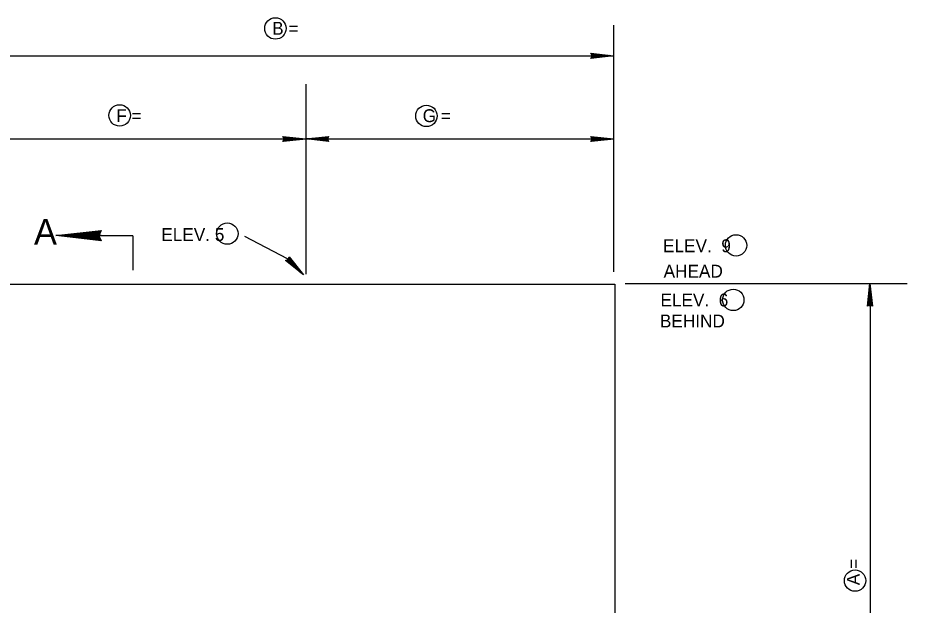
# Model space of a CAD drawing. Extents: x 1.6 to 6.29, y 2.8 to 7.08.
# Drawn here: x 2.935 to 3.8, y 5.479 to 6.051 of the extents above; entities that cross this region are included whole.
import ezdxf

# ---------------------------------------------------------------- set-up
doc = ezdxf.new("R2010")
doc.units = 0
doc.layers.add('Level 1', color=7, linetype='Continuous')
doc.layers.add('Level 5', color=7, linetype='Continuous')

msp = doc.modelspace()

# ---------------------------------------------------------------- linework, layer by layer
at = {"layer": 'Level 1'}
for p, q in [((3.51433, 5.80408), (3.51433, 6.04392)), ((2.90767, 6.01425), (3.22592, 6.01425)), ((3.22592, 6.01425), (3.51225, 6.01425)), ((3.492, 6.01667), (3.51425, 6.01425)), ((3.49317, 6.01425), (3.492, 6.01667)), ((3.492, 6.01425), (3.51425, 6.01425)), ((3.51425, 6.01425), (3.492, 6.01175)), ((3.492, 6.01175), (3.49317, 6.01425)), ((3.49233, 6.01283), (3.50783, 6.0145)), ((3.49242, 6.01633), (3.509, 6.0145)), ((3.49242, 6.01625), (3.509, 6.01442)), ((3.49242, 6.01617), (3.509, 6.01433)), ((3.49242, 6.01592), (3.509, 6.01408)), ((3.49242, 6.01258), (3.50783, 6.01425)), ((3.49242, 6.01233), (3.50792, 6.014)), ((3.4925, 6.01642), (3.509, 6.01458)), ((3.4925, 6.01208), (3.50792, 6.01383)), ((3.49292, 6.01325), (3.4925, 6.01217)), ((3.49358, 6.01442), (3.49258, 6.016)), ((3.49258, 6.016), (3.49308, 6.01567)), ((3.49333, 6.01417), (3.49292, 6.01325)), ((3.49783, 6.01517), (3.493, 6.01542)), ((3.493, 6.01542), (3.50067, 6.01483)), ((3.49308, 6.01567), (3.49358, 6.01483)), ((3.5045, 6.01442), (3.49308, 6.01325)), ((3.49308, 6.01325), (3.49358, 6.01442)), ((3.49325, 6.015), (3.49783, 6.01517)), ((3.49992, 6.01483), (3.49325, 6.015)), ((3.49325, 6.01367), (3.5045, 6.01442)), ((3.49867, 6.01367), (3.49325, 6.01367)), ((3.49367, 6.01575), (3.49333, 6.01417)), ((3.4935, 6.01467), (3.49992, 6.01483)), ((3.4935, 6.0145), (3.50342, 6.01467)), ((3.5015, 6.0145), (3.4935, 6.01467)), ((3.51125, 6.01408), (3.4935, 6.014)), ((3.4935, 6.014), (3.49867, 6.01367)), ((3.49358, 6.01483), (3.49408, 6.01508)), ((3.49408, 6.01508), (3.49367, 6.01575)), ((3.50067, 6.01483), (3.5105, 6.01442)), ((3.50333, 6.01442), (3.5015, 6.0145)), ((3.50342, 6.01467), (3.50333, 6.01442)), ((3.5105, 6.01442), (3.5085, 6.01383)), ((3.5085, 6.01383), (3.51125, 6.01408)), ((3.21483, 5.98658), (3.21483, 5.80158)), ((3.1925, 5.93567), (3.21475, 5.93325)), ((3.19367, 5.93325), (3.1925, 5.93567)), ((3.19292, 5.93533), (3.2095, 5.9335)), ((3.19292, 5.93525), (3.2095, 5.93342)), ((3.19292, 5.93517), (3.2095, 5.93333)), ((3.19292, 5.93492), (3.2095, 5.93308)), ((3.193, 5.93542), (3.2095, 5.93358)), ((3.19408, 5.93342), (3.19308, 5.935)), ((3.19308, 5.935), (3.19358, 5.93467)), ((3.19358, 5.93467), (3.19408, 5.93383)), ((3.19417, 5.93475), (3.19383, 5.93317)), ((3.19458, 5.93408), (3.19417, 5.93475)), ((3.21492, 5.93325), (3.237, 5.93575)), ((3.2365, 5.93533), (3.22117, 5.93367)), ((3.2365, 5.93517), (3.22117, 5.9335)), ((3.23658, 5.93492), (3.22125, 5.93325)), ((3.23658, 5.93467), (3.22125, 5.933)), ((3.237, 5.93575), (3.23583, 5.93325)), ((3.236, 5.93425), (3.2365, 5.93533)), ((3.49208, 5.93567), (3.51433, 5.93325)), ((3.49325, 5.93325), (3.49208, 5.93567)), ((3.4925, 5.93533), (3.50908, 5.9335)), ((3.4925, 5.93525), (3.50908, 5.93342)), ((3.4925, 5.93517), (3.50908, 5.93333)), ((3.4925, 5.93492), (3.50908, 5.93308)), ((3.49258, 5.93542), (3.50908, 5.93358)), ((3.49367, 5.93342), (3.49267, 5.935)), ((3.49267, 5.935), (3.49317, 5.93467)), ((3.49317, 5.93467), (3.49367, 5.93383)), ((3.49375, 5.93475), (3.49342, 5.93317)), ((3.49417, 5.93408), (3.49375, 5.93475)), ((2.90767, 5.93325), (3.51433, 5.93325)), ((3.1925, 5.93325), (3.21475, 5.93325)), ((3.21475, 5.93325), (3.1925, 5.93075)), ((3.1925, 5.93075), (3.19367, 5.93325)), ((3.19283, 5.93183), (3.20833, 5.9335)), ((3.19292, 5.93158), (3.20833, 5.93325)), ((3.19292, 5.93133), (3.20842, 5.933)), ((3.193, 5.93108), (3.20842, 5.93283)), ((3.19342, 5.93225), (3.193, 5.93117)), ((3.19383, 5.93317), (3.19342, 5.93225)), ((3.19833, 5.93417), (3.1935, 5.93442)), ((3.1935, 5.93442), (3.20117, 5.93383)), ((3.205, 5.93342), (3.19358, 5.93225)), ((3.19358, 5.93225), (3.19408, 5.93342)), ((3.19375, 5.934), (3.19833, 5.93417)), ((3.20042, 5.93383), (3.19375, 5.934)), ((3.19375, 5.93267), (3.205, 5.93342)), ((3.19917, 5.93267), (3.19375, 5.93267)), ((3.194, 5.93367), (3.20042, 5.93383)), ((3.194, 5.9335), (3.20392, 5.93367)), ((3.202, 5.9335), (3.194, 5.93367)), ((3.21175, 5.93308), (3.194, 5.933)), ((3.194, 5.933), (3.19917, 5.93267)), ((3.19408, 5.93383), (3.19458, 5.93408)), ((3.20117, 5.93383), (3.211, 5.93342)), ((3.20383, 5.93342), (3.202, 5.9335)), ((3.20392, 5.93367), (3.20383, 5.93342)), ((3.211, 5.93342), (3.209, 5.93283)), ((3.209, 5.93283), (3.21175, 5.93308)), ((3.237, 5.93325), (3.21492, 5.93325)), ((3.237, 5.93083), (3.21492, 5.93325)), ((3.22058, 5.93367), (3.21792, 5.93342)), ((3.21792, 5.93342), (3.2355, 5.9335)), ((3.21858, 5.93308), (3.22058, 5.93367)), ((3.22842, 5.93267), (3.21858, 5.93308)), ((3.2365, 5.93117), (3.22008, 5.933)), ((3.2365, 5.93125), (3.22008, 5.933)), ((3.2365, 5.93108), (3.22008, 5.93292)), ((3.23658, 5.93158), (3.22017, 5.93333)), ((3.2365, 5.93133), (3.22017, 5.93317)), ((3.2245, 5.933), (3.23583, 5.93425)), ((3.23575, 5.93383), (3.2245, 5.933)), ((3.22567, 5.93283), (3.22567, 5.93308)), ((3.22567, 5.93308), (3.22758, 5.933)), ((3.2355, 5.933), (3.22567, 5.93283)), ((3.22758, 5.933), (3.2355, 5.93283)), ((3.23592, 5.93208), (3.22842, 5.93267)), ((3.2355, 5.93283), (3.22917, 5.93267)), ((3.22917, 5.93267), (3.23575, 5.9325)), ((3.2355, 5.9335), (3.23033, 5.93383)), ((3.23033, 5.93383), (3.23575, 5.93383)), ((3.23575, 5.9325), (3.23108, 5.93233)), ((3.23108, 5.93233), (3.23592, 5.93208)), ((3.23542, 5.93267), (3.23483, 5.93242)), ((3.23483, 5.93242), (3.23525, 5.93175)), ((3.23525, 5.93175), (3.23558, 5.93333)), ((3.23583, 5.93425), (3.23542, 5.933)), ((3.23542, 5.933), (3.23633, 5.9315)), ((3.23583, 5.93183), (3.23542, 5.93267)), ((3.23558, 5.93333), (3.236, 5.93425)), ((3.23583, 5.93325), (3.237, 5.93083)), ((3.23633, 5.9315), (3.23583, 5.93183)), ((3.49208, 5.93325), (3.51433, 5.93325)), ((3.51433, 5.93325), (3.49208, 5.93075)), ((3.49208, 5.93075), (3.49325, 5.93325)), ((3.49242, 5.93183), (3.50792, 5.9335)), ((3.4925, 5.93158), (3.50792, 5.93325)), ((3.4925, 5.93133), (3.508, 5.933)), ((3.49258, 5.93108), (3.508, 5.93283)), ((3.493, 5.93225), (3.49258, 5.93117)), ((3.49342, 5.93317), (3.493, 5.93225)), ((3.49792, 5.93417), (3.49308, 5.93442)), ((3.49308, 5.93442), (3.50075, 5.93383)), ((3.50458, 5.93342), (3.49317, 5.93225)), ((3.49317, 5.93225), (3.49367, 5.93342)), ((3.49333, 5.934), (3.49792, 5.93417)), ((3.5, 5.93383), (3.49333, 5.934)), ((3.49333, 5.93267), (3.50458, 5.93342)), ((3.49875, 5.93267), (3.49333, 5.93267)), ((3.49358, 5.93367), (3.5, 5.93383)), ((3.49358, 5.9335), (3.5035, 5.93367)), ((3.50158, 5.9335), (3.49358, 5.93367)), ((3.51133, 5.93308), (3.49358, 5.933)), ((3.49358, 5.933), (3.49875, 5.93267)), ((3.49367, 5.93383), (3.49417, 5.93408)), ((3.50075, 5.93383), (3.51058, 5.93342)), ((3.50342, 5.93342), (3.50158, 5.9335)), ((3.5035, 5.93367), (3.50342, 5.93342)), ((3.51058, 5.93342), (3.50858, 5.93283)), ((3.50858, 5.93283), (3.51133, 5.93308)), ((2.97158, 5.83917), (3.01575, 5.84408)), ((2.983, 5.83992), (2.97758, 5.83942)), ((2.97758, 5.83942), (3.01275, 5.83958)), ((2.97892, 5.83883), (2.983, 5.83992)), ((3.01475, 5.84333), (2.98408, 5.84)), ((3.01483, 5.84292), (2.98417, 5.83958)), ((3.01492, 5.84242), (2.98433, 5.83908)), ((3.015, 5.84192), (2.98433, 5.83858)), ((2.99083, 5.83867), (3.0135, 5.84117)), ((3.01333, 5.84025), (2.99083, 5.83867)), ((3.01275, 5.83958), (3.0025, 5.84025)), ((3.0025, 5.84025), (3.01333, 5.84025)), ((3.0135, 5.84117), (3.01267, 5.83867)), ((3.01292, 5.83925), (3.01383, 5.84117)), ((3.01575, 5.84408), (3.01342, 5.83908)), ((3.01383, 5.84117), (3.01475, 5.84333)), ((3.01575, 5.83917), (2.97158, 5.83917)), ((3.01575, 5.83425), (2.97158, 5.83917)), ((2.99858, 5.838), (2.97892, 5.83883)), ((3.01483, 5.83517), (2.98192, 5.83867)), ((3.01483, 5.835), (2.98192, 5.83858)), ((3.01475, 5.83483), (2.98192, 5.83842)), ((3.01492, 5.83575), (2.98208, 5.83933)), ((3.01483, 5.83533), (2.98208, 5.839)), ((2.99308, 5.83833), (2.99317, 5.83883)), ((3.01275, 5.83858), (2.99308, 5.83833)), ((2.99317, 5.83883), (2.997, 5.83858)), ((2.997, 5.83858), (3.01275, 5.83833)), ((3.01367, 5.83683), (2.99858, 5.838)), ((3.01275, 5.83833), (3.00008, 5.83792)), ((3.00008, 5.83792), (3.01333, 5.83767)), ((3.01333, 5.83767), (3.004, 5.83733)), ((3.004, 5.83733), (3.01367, 5.83683)), ((3.01267, 5.838), (3.0115, 5.8375)), ((3.0115, 5.8375), (3.01225, 5.83608)), ((3.01225, 5.83608), (3.01292, 5.83925)), ((3.01267, 5.83867), (3.0145, 5.83558)), ((3.0135, 5.83625), (3.01267, 5.838)), ((3.01342, 5.83908), (3.01575, 5.83425)), ((3.0145, 5.83558), (3.0135, 5.83625)), ((3.04658, 5.839), (3.014, 5.839)), ((3.04658, 5.839), (3.04658, 5.80558)), ((3.19517, 5.81492), (3.19775, 5.81583)), ((3.21267, 5.80092), (3.19517, 5.81492)), ((3.19575, 5.81483), (3.20792, 5.80517)), ((3.19692, 5.81533), (3.19583, 5.81483)), ((3.19592, 5.815), (3.208, 5.80525)), ((3.19608, 5.81525), (3.20817, 5.8055)), ((3.19617, 5.81542), (3.20833, 5.80567)), ((3.19692, 5.81667), (3.21267, 5.80092)), ((3.19783, 5.81567), (3.19692, 5.81533)), ((3.197, 5.81525), (3.19817, 5.81567)), ((3.20592, 5.808), (3.197, 5.81525)), ((3.20125, 5.81158), (3.19742, 5.81542)), ((3.19742, 5.81542), (3.20592, 5.808)), ((3.19775, 5.81583), (3.19867, 5.81842)), ((3.19917, 5.81658), (3.19783, 5.81567)), ((3.21042, 5.80292), (3.19783, 5.81542)), ((3.19783, 5.81542), (3.20125, 5.81158)), ((3.19817, 5.81567), (3.19858, 5.8175)), ((3.19817, 5.81583), (3.20533, 5.80892)), ((3.203, 5.8115), (3.19833, 5.81633)), ((3.19833, 5.81633), (3.20175, 5.81317)), ((3.20383, 5.81017), (3.19833, 5.81592)), ((3.19833, 5.81592), (3.203, 5.8115)), ((3.19842, 5.81758), (3.20883, 5.80458)), ((3.19875, 5.81692), (3.1985, 5.816)), ((3.20175, 5.81317), (3.1985, 5.81683)), ((3.1985, 5.81683), (3.2035, 5.811)), ((3.1985, 5.816), (3.199, 5.81583)), ((3.19858, 5.81775), (3.209, 5.80475)), ((3.19858, 5.8175), (3.19875, 5.81692)), ((3.19867, 5.81842), (3.21267, 5.80092)), ((3.19867, 5.81783), (3.20908, 5.80475)), ((3.19875, 5.81783), (3.20917, 5.80483)), ((3.19883, 5.81783), (3.20917, 5.80492)), ((3.199, 5.81583), (3.19917, 5.81658)), ((3.2035, 5.811), (3.21017, 5.80375)), ((3.20508, 5.80875), (3.20383, 5.81017)), ((3.20533, 5.80892), (3.20508, 5.80875)), ((3.21017, 5.80375), (3.20833, 5.80475)), ((3.20833, 5.80475), (3.21042, 5.80292)), ((2.91025, 5.79208), (3.22917, 5.79208)), ((3.22917, 5.79208), (3.51525, 5.79208)), ((3.51525, 5.792), (3.51525, 5.28792)), ((3.5255, 5.7925), (3.79975, 5.7925)), ((3.76108, 5.77042), (3.7635, 5.7925)), ((3.76292, 5.779), (3.76342, 5.78883)), ((3.76342, 5.78883), (3.76392, 5.78675)), ((3.7635, 5.77042), (3.7635, 5.7925)), ((3.7635, 5.7925), (3.766, 5.77042)), ((3.76392, 5.78675), (3.76367, 5.7895)), ((3.76367, 5.7895), (3.76375, 5.77192)), ((3.76367, 5.78783), (3.76367, 5.13442)), ((3.76142, 5.77092), (3.76317, 5.78733)), ((3.76142, 5.77083), (3.76325, 5.78733)), ((3.7615, 5.77083), (3.76333, 5.78733)), ((3.76167, 5.77083), (3.76342, 5.78725)), ((3.76183, 5.77083), (3.76367, 5.78725)), ((3.76242, 5.77142), (3.76292, 5.779)), ((3.76325, 5.77192), (3.76308, 5.78175)), ((3.76308, 5.78175), (3.76342, 5.78167)), ((3.76325, 5.77983), (3.76308, 5.77192)), ((3.76492, 5.77075), (3.76325, 5.78608)), ((3.76342, 5.78167), (3.76325, 5.77983)), ((3.76408, 5.77167), (3.76333, 5.78292)), ((3.76333, 5.78292), (3.7645, 5.7715)), ((3.76517, 5.77083), (3.7635, 5.78617)), ((3.76542, 5.77083), (3.76375, 5.78625)), ((3.76567, 5.77092), (3.76392, 5.78625)), ((3.7635, 5.77158), (3.76108, 5.77042)), ((3.76333, 5.772), (3.76175, 5.771)), ((3.76175, 5.771), (3.76208, 5.7715)), ((3.76275, 5.7725), (3.762, 5.77217)), ((3.762, 5.77217), (3.76358, 5.77183)), ((3.76208, 5.7715), (3.76292, 5.772)), ((3.76267, 5.77625), (3.76242, 5.77142)), ((3.76275, 5.77167), (3.76267, 5.77625)), ((3.76292, 5.77825), (3.76275, 5.77167)), ((3.76292, 5.772), (3.76275, 5.7725)), ((3.76308, 5.77192), (3.76292, 5.77825)), ((3.7645, 5.7715), (3.76333, 5.772)), ((3.766, 5.77042), (3.7635, 5.77158)), ((3.76358, 5.77183), (3.7645, 5.77142)), ((3.76375, 5.77192), (3.76408, 5.77708)), ((3.76408, 5.77708), (3.76408, 5.77167)), ((3.7645, 5.77142), (3.76558, 5.77092))]:
    msp.add_line(p, q, dxfattribs=at)
for centre in [(3.18521, 6.04081), (3.03371, 5.95615), (3.33212, 5.95573), (3.13846, 5.84115), (3.63329, 5.82965), (3.63054, 5.77665), (3.74902, 5.50338)]:
    msp.add_circle(centre, 0.01042, dxfattribs=at)
at = {"layer": 'Level 5'}
msp.add_line((3.19692, 5.81667), (3.15533, 5.83833), dxfattribs=at)

# ---------------------------------------------------------------- texts
at = {"layer": 'Level 1'}
for s, height, p in [('A', 0.025, (2.95042, 5.83042)), ('ELEV. 5', 0.0125, (3.07425, 5.834))]:
    msp.add_text(s, height=height, dxfattribs=at).set_placement(p)
at = {"layer": 'Level 5'}
for s, p in [('B =      ', (3.18208, 6.03475)), ('F =      ', (3.0305, 5.94967)), ('G =      ', (3.3285, 5.94967)), ('ELEV.  9', (3.56225, 5.82308)), ('AHEAD', (3.56283, 5.79833)), ('ELEV.  6', (3.55975, 5.77025)), ('BEHIND', (3.55925, 5.74983))]:
    msp.add_text(s, height=0.0125, dxfattribs=at).set_placement(p)
msp.add_text('A =      ', height=0.0125, rotation=90, dxfattribs=at).set_placement((3.75358, 5.49892))

doc.saveas('drawing.dxf')
